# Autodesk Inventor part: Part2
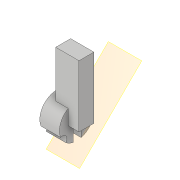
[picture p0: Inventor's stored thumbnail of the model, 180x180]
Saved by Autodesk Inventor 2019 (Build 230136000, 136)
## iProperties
Created: 2018-04
Part Number: Part2
Material: Generic
Document SubType Name: Modeling
Designer: CADCIM 00
Density: 1 g/cm^3
Appearance: Default
Author: CADCIM 00
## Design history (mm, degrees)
sketch "Sketch1"
  geometry: L1 (0, 0)-(11.639, 0); L2 (11.639, 0)-(11.639, 13.293); L3 (11.639, 13.293)-(0, 13.293); L4 (0, 13.293)-(0, 0)
  constraints: 8 end point, 2 parallel, 1 horizontal, 1 perpendicular
revolve "Revolution1" sketch "Sketch1" stored, may be unused: angle "d0" = 90 deg
sketch "Sketch2"
  geometry: C1 r 3.023 at (9.664, -7.029); 1 further point
  constraints: 1 centre point
extrude "Extrusion1" cut sketch "Sketch2" distance "d1" = 41.75; taper "d2" = 0 deg
sketch "Sketch3"
  geometry: L1 (-5.666, -7.253)-(4.42, -7.253); L2 (4.42, -7.253)-(4.42, 8.5); L3 (4.42, 8.5)-(-5.666, 8.5); L4 (-5.666, 8.5)-(-5.666, -7.253); 1 further point
  constraints: 8 end point, 2 parallel, 1 horizontal, 1 perpendicular
extrude "Extrusion2" join sketch "Sketch3" distance "d3" = 41.75; taper "d4" = 0 deg
sketch "Sketch4"
  geometry: L1 (-13.634, 2.329)-(0.744, 2.329); L2 (0.744, 2.329)-(0.744, -3.038); L3 (0.744, -3.038)-(-13.634, -3.038); L4 (-13.634, -3.038)-(-13.634, 2.329); 1 further point
  constraints: 8 end point, 2 parallel, 1 horizontal, 1 perpendicular
extrude "Extrusion3" cut sketch "Sketch4" distance "d5" = 43.5; taper "d6" = 0 deg
workplane "Work Plane1"
body "Solid1"
other parameters: "d7" = 45 deg
